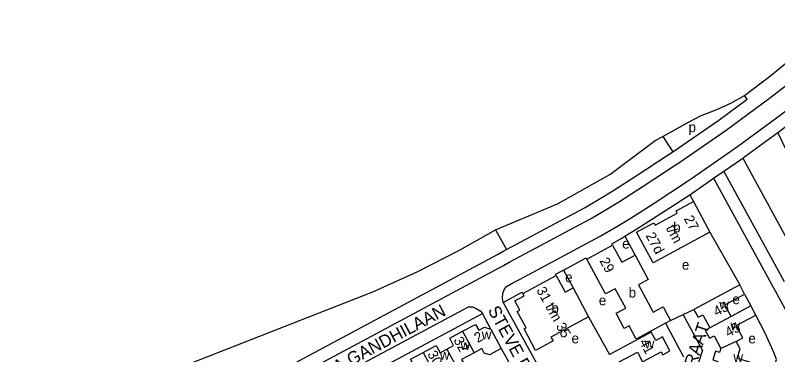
# Model space of a CAD drawing. Extents: x 157794 to 159375, y 380877 to 382306.
# Drawn here: x 158861.6 to 159166.5, y 382048.3 to 382184.1 of the extents above; entities that cross this region are included whole.
import ezdxf

# ---------------------------------------------------------------- set-up
doc = ezdxf.new("R2010")
doc.units = 0
for name, color, linetype in [('BLT_Basislijn', 7, 'Continuous'), ('BLT_Bebouwing', 7, 'Continuous'), ('BLT_Centroide', 7, 'Continuous'), ('BLT_Huisnummer', 7, 'Continuous'), ('BLT_Huisnummer_ tussenligend', 7, 'Continuous'), ('BLT_Huisnummer_reeks', 7, 'Continuous'), ('BLT_Onderverdeling_panden', 7, 'Continuous'), ('BLT_Straatnaam', 7, 'Continuous')]:
    doc.layers.add(name, color=color, linetype=linetype)

msp = doc.modelspace()

# ---------------------------------------------------------------- linework, layer by layer
at = {"layer": 'BLT_Basislijn'}
for p, q in [((159120.46, 382135.68), (159124.57, 382129.56)), ((159131.28, 382112.37), (159132.75, 382109.61)), ((159053.65, 382098.28), (159057.98, 382090.42)), ((159105.35, 382095.75), (159109.43, 382088.21)), ((159139.38, 382097.32), (159151.26, 382076.31)), ((159080.78, 382082.22), (159084.62, 382075.05)), ((159169.21, 382077.46), (159166.09, 382083.17)), ((159153.24, 382072.58), (159155.76, 382067.89)), ((159128.71, 382064.48), (159132.92, 382066.49)), ((159051.81, 382058.6), (159048.45, 382064.86)), ((159090.83, 382063.47), (159099.27, 382048.44)), ((159123.61, 382062.03), (159128.71, 382064.48)), ((159136.42, 382050.21), (159128.71, 382064.48)), ((159121.59, 382060.94), (159128.85, 382047.44)), ((159055.96, 382050.89), (159068.83, 382027.6)), ((159136.42, 382050.21), (159110.16, 381970.11))]:
    msp.add_line(p, q, dxfattribs=at)
for points in [[(159153.13, 382152.04), (159163.76, 382160.06), (159174.94, 382169.27), (159188.37, 382180.32), (159189.89, 382181.55), (159193.04, 382184.14)], [(158861.64, 381979.44), (158865.56, 381981.52), (158907.88, 382004.25), (158914, 382007.54), (159056.77, 382084.07), (159059.38, 382085.5), (159091.58, 382102.75), (159097.42, 382106.14), (159103.19, 382109.67), (159112.65, 382115.73), (159125.89, 382124.38), (159127.38, 382125.43), (159145.8, 382138.15), (159163.12, 382150.91), (159179.42, 382163.47), (159183.59, 382166.45), (159186.15, 382168.04), (159188.85, 382169.38), (159189.71, 382169.79), (159191.99, 382170.85), (159192.34, 382170.99), (159195.08, 382172.13), (159196.82, 382172.94)], [(159056.72, 382069.29), (159056.47, 382071.01), (159056.6, 382072.94), (159057.2, 382074.56), (159058.04, 382075.67), (159060.59, 382077.04), (159063.19, 382078.47), (159095.48, 382095.76), (159101.52, 382099.27), (159107.43, 382102.88), (159117, 382109.01), (159130.38, 382117.76), (159131.95, 382118.86), (159150.44, 382131.64), (159167.94, 382144.52), (159184.19, 382157.04), (159184.32, 382157.14)], [(159120.46, 382135.68), (159129.29, 382140.63), (159135.55, 382143.86), (159142.11, 382146.4), (159147.77, 382148.93), (159153.13, 382152.04)], [(159124.57, 382129.56), (159142.89, 382142.22), (159154.22, 382150.57), (159153.13, 382152.04)], [(159166.47, 382137.23), (159170.94, 382140.53), (159187.17, 382153.03), (159187.46, 382153.27)], [(159152.5, 382126.98), (159173.48, 382088.59), (159173.96, 382087.78), (159174.92, 382087.45), (159233.92, 382125.82), (159234.06, 382126.76), (159225.93, 382139.39)], [(159053.65, 382098.28), (159078.43, 382108.77), (159099.34, 382120.43), (159117.44, 382133.99), (159120.46, 382135.68)], [(159152.5, 382126.98), (159153.35, 382127.57), (159166.47, 382137.23)], [(159173.35, 382123.12), (159166.47, 382137.23)], [(159057.98, 382090.42), (159089.15, 382107.11), (159094.86, 382110.44), (159100.53, 382113.9), (159109.93, 382119.92), (159123.09, 382128.52), (159124.57, 382129.56)], [(159144.95, 382121.77), (159152.5, 382126.98)], [(159140.82, 382118.91), (159144.95, 382121.77)], [(159166.09, 382083.17), (159144.95, 382121.77)], [(159131.28, 382112.37), (159133.18, 382113.62), (159134.81, 382114.76), (159140.82, 382118.91)], [(159140.82, 382118.91), (159177.84, 382051.3), (159175.46, 382048.68), (159173.85, 382046.26), (159170.14, 382038.9), (159163.94, 382024.57), (159158.85, 382008.03), (159155.39, 381990.51), (159154.46, 381978.1)], [(159105.35, 382095.75), (159110.08, 382098.64), (159119.71, 382104.81), (159131.28, 382112.37)], [(158872.47, 382014.55), (158874.39, 382016.74), (158876, 382018.39), (158878.28, 382020.48), (158881.01, 382022.61), (158883.71, 382024.38), (158886.62, 382025.98), (158886.91, 382026.11), (158895.95, 382030.32), (158914.54, 382038.11), (158931.77, 382045), (158986.2, 382066.29), (159004.58, 382073.57), (159022.64, 382081.6), (159039.22, 382090.22), (159053.65, 382098.28)], [(159100.39, 382092.13), (159100.08, 382092.65), (159104.08, 382094.98), (159105.35, 382095.75)], [(158864.15, 381986.44), (158905.51, 382008.66), (158911.63, 382011.95), (159054.39, 382088.46), (159056.99, 382089.9), (159057.98, 382090.42)], [(159080.78, 382082.22), (159089.85, 382087.07), (159090.12, 382086.57)], [(159077.9, 382080), (159077.62, 382080.52), (159080.78, 382082.22)], [(159056.72, 382069.29), (159062.98, 382072.64), (159064.29, 382073.37), (159064.56, 382072.88)], [(159056.72, 382069.29), (159075.06, 382035.72)], [(158949.67, 382017.58), (159042.84, 382067.52), (159044.41, 382067.5), (159045.94, 382066.86), (159047.44, 382065.95), (159048.45, 382064.86)], [(158949.21, 382011.67), (159048.45, 382064.86)], [(159135.96, 381957.35), (159138.34, 381964.55), (159139.55, 381968.13), (159141.32, 381973.39), (159142.6, 381977.17), (159144.4, 381982.38), (159145.64, 381986.1), (159147.51, 381991.59), (159166.01, 382046.42), (159165.07, 382048.93), (159161.39, 382056.95), (159157.72, 382064.21)]]:
    msp.add_lwpolyline(points, dxfattribs=at)
at = {"layer": 'BLT_Bebouwing'}
for p, q in [((159132.75, 382109.61), (159139.38, 382097.32)), ((159084.62, 382075.05), (159090.83, 382063.47)), ((159151.26, 382076.31), (159132.92, 382066.49)), ((159153.24, 382072.58), (159151.26, 382076.31)), ((159155.76, 382067.89), (159147.84, 382063.67)), ((159157.72, 382064.21), (159155.76, 382067.89)), ((159123.61, 382062.03), (159121.59, 382060.94)), ((159099.27, 382048.44), (159099.01, 382048.3))]:
    msp.add_line(p, q, dxfattribs=at)
for points in [[(159139.38, 382097.32), (159116.6, 382085.04), (159109.97, 382097.33), (159116.9, 382101.07), (159117.42, 382100.12), (159126.3, 382104.91), (159125.79, 382105.86), (159132.75, 382109.61)], [(159090.12, 382086.57), (159100.39, 382092.13)], [(159100.39, 382092.13), (159104.08, 382085.31), (159109.43, 382088.21)], [(159121.59, 382060.94), (159109.88, 382054.6), (159107.01, 382059.9), (159105.1, 382058.87), (159101.81, 382064.93), (159105.68, 382067.03), (159101.52, 382074.72), (159097.66, 382072.64), (159090.12, 382086.57)], [(159109.43, 382088.21), (159114.72, 382078.44), (159110.8, 382076.32), (159116.71, 382065.39), (159120.63, 382067.51), (159123.61, 382062.03)], [(159064.56, 382072.88), (159077.9, 382080)], [(159077.9, 382080), (159081.46, 382073.32), (159084.62, 382075.05)], [(159090.83, 382063.47), (159075.8, 382055.43), (159076.65, 382053.84), (159069.67, 382050.1), (159065.08, 382058.67), (159065.85, 382059.08), (159062.35, 382065.58), (159063.36, 382066.12), (159061.35, 382069.86), (159065.1, 382071.87), (159064.56, 382072.88)], [(159147.84, 382063.67), (159145.34, 382068.35), (159153.24, 382072.58)], [(159132.92, 382066.49), (159134.64, 382063.31), (159136.56, 382064.33), (159139.33, 382059.12)], [(159149.81, 382053.61), (159152.47, 382055.09), (159149.78, 382059.99), (159157.72, 382064.21)], [(159040.46, 382057.72), (159045.62, 382060.49), (159046.9, 382058.11), (159049.24, 382059.37), (159051.81, 382058.6)], [(159139.33, 382059.12), (159137.41, 382058.08), (159139.12, 382054.92), (159141.05, 382055.94), (159143.74, 382050.87)], [(159034.19, 382050.55), (159036.89, 382052.01), (159035.31, 382054.96), (159040.46, 382057.72)], [(159051.81, 382058.6), (159055.96, 382050.89)], [(159115.84, 382057.33), (159100, 382048.83), (159099.27, 382048.44)], [(159101.09, 382044.41), (159110.37, 382049.38), (159112.46, 382045.52), (159119.87, 382049.46), (159120.46, 382048.34), (159123.35, 382049.89), (159120.38, 382055.5), (159117.67, 382054), (159115.84, 382057.33)], [(159149.83, 382037.17), (159151.48, 382042.23), (159161.14, 382039.03), (159162.45, 382042.98), (159150.19, 382046.99), (159151.39, 382050.64), (159149.81, 382053.61)], [(159024.77, 382049.29), (159029.92, 382052.04), (159031.5, 382049.1), (159034.19, 382050.55)], [(159055.96, 382050.89), (159051.28, 382048.37), (159049.13, 382049.01), (159048.15, 382050.83), (159045.05, 382049.17)], [(159143.74, 382050.87), (159143.24, 382049.26), (159141.57, 382049.79), (159140.45, 382046.36), (159142.51, 382045.68), (159140.65, 382040.08)], [(159019.77, 382039.83), (159022.46, 382041.27), (159019.63, 382046.54), (159024.77, 382049.29)], [(159045.05, 382049.17), (159040.08, 382046.5), (159041.32, 382044.19), (159038.43, 382042.64)]]:
    msp.add_lwpolyline(points, dxfattribs=at)
at = {"layer": 'BLT_Onderverdeling_panden'}
for p, q in [((159147.84, 382063.67), (159139.33, 382059.12)), ((159040.46, 382057.72), (159045.05, 382049.17)), ((159149.81, 382053.61), (159143.74, 382050.87)), ((159034.19, 382050.55), (159038.43, 382042.64)), ((159024.77, 382049.29), (159029.35, 382040.73))]:
    msp.add_line(p, q, dxfattribs=at)

# ---------------------------------------------------------------- texts
at = {"layer": 'BLT_Centroide'}
for s, p in [('p', (159130.81, 382137.38)), ('b', (159124.67, 382097.31)), ('e', (159104.29, 382090.8)), ('e', (159128.15, 382082.36)), ('e', (159081.46, 382077.37)), ('b', (159106.86, 382071.22)), ('e', (159094.94, 382068.12)), ('e', (159148.32, 382068.58)), ('b', (159075.98, 382065.06)), ('w', (159143.08, 382066.53)), ('w', (159147.56, 382058.06)), ('w', (159048.15, 382054.44)), ('e', (159084.03, 382052.94)), ('e', (159154.72, 382052.89)), ('w', (159039.62, 382050.28)), ('w', (159113.31, 382050.88)), ('w', (159031.38, 382046.38)), ('w', (159148.74, 382045.38))]:
    msp.add_text(s, height=4, dxfattribs=at).set_placement(p)
at = {"layer": 'BLT_Huisnummer'}
for s, rotation, p in [('29', 298.4391, (159095.1, 382085.92)), ('43', 28.1165, (159142.04, 382063.55)), ('45', 28.9942, (159146.76, 382055.23)), ('2', 28.2598, (159046.43, 382052.98)), ('32', 298.2475, (159036.73, 382054.23)), ('41', 298.55, (159110.97, 382053.43))]:
    msp.add_text(s, height=4, rotation=rotation, dxfattribs=at).set_placement(p)
at = {"layer": 'BLT_Huisnummer_ tussenligend'}
msp.add_text('30', height=4, rotation=298.2475, dxfattribs=at).set_placement((159026.29, 382048.69))
at = {"layer": 'BLT_Huisnummer_reeks'}
for s, rotation, p in [('27', 298.3449, (159128.8, 382102.8)), ('t/m', 298.3399, (159121.62, 382099.08)), ('27d', 298.3449, (159113.55, 382096.03)), ('31 t/m 35', 298.55, (159069.86, 382074.21))]:
    msp.add_text(s, height=4, rotation=rotation, dxfattribs=at).set_placement(p)
at = {"layer": 'BLT_Straatnaam'}
for s, height, rotation, p in [('MAHATMA GANDHILAAN', 5, 28.0837, (158964.75, 382027.28)), ('STEVE BIKOSTRAAT', 5, 298.4051, (159050.43, 382066.23)), ('MARTIN LUTHER KINGSTRAAT', 4.9999, 71.5304, (159107.99, 381966.37))]:
    msp.add_text(s, height=height, rotation=rotation, dxfattribs=at).set_placement(p)

doc.saveas('drawing.dxf')
